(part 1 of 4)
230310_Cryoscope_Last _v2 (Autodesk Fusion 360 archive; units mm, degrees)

design "230310_Cryoscope_Last" references "P300_M-Step", "001_LED_Input", "001_CM_Imaging", "001_CM_Excitation", "DIN912 M4 x 18", "VAP4_M-Step", "Arduino Triggerbox main", "MB3045_M-Step", "Zeiss_CMS_mount", "Zeiss_dovetail", "LED_combiner_mount", "001_CM_Objective", "DIN912 M4 x 48", "Optical Table Assembly", "Linkam stage approximate", "M4 Hex nut"
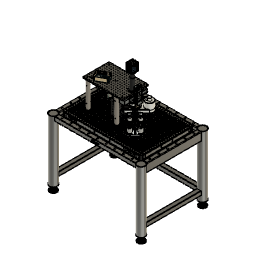
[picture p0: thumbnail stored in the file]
component_insert "Component Insert2"
sketch "Sketch1" plane through (0, 0, -72.86) normal (0, 0, 1) x axis (-1, 0, 0)
  line L1 (-212.7048, -83.1723) -> (-237.1448, -83.1723)
  line L2 (-212.7048, -59.1973) -> (-212.7048, -83.1723)
  line L3 (-177.1448, -52.8473) -> (-206.3548, -52.8473)
  line L4 (-177.1448, 7.1527) -> (-177.1448, -52.8473)
  line L5 (-206.3548, 7.1527) -> (-177.1448, 7.1527)
  line L6 (-212.7048, 37.4777) -> (-212.7048, 13.5027)
  line L7 (-237.1448, 37.4777) -> (-212.7048, 37.4777)
  line L8 (-237.1448, -83.1723) -> (-237.1448, 37.4777)
  arc A1 centre (-206.3548, -59.1973) radius 6.35 clockwise from (-212.7048, -59.1973) to (-206.3548, -52.8473)
  arc A2 centre (-206.3548, 13.5027) radius 6.35 clockwise from (-206.3548, 7.1527) to (-212.7048, 13.5027)
  circle C1 centre (-197.3988, -22.8473) radius 19.05
  circle C2 centre (-227.1372, -72.8472) radius 4
  circle C3 centre (-227.1372, 27.1526) radius 4
component_insert "Component Insert10"
component_insert "Component Insert11"
base_feature "Base Feature"
component_insert "Component Insert13"
component_insert "Component Insert14"
component_insert "Component Insert15"
component_insert "Component Insert18"
component_insert "Component Insert19"
position "Position3"
sketch "Sketch2" plane through (0, 0, -72.86) normal (0, 0, 1) x axis (-1, 0, 0)
  line L1 (-212.7048, -83.1723) -> (-237.1448, -83.1723)
  line L2 (-212.7048, -59.1973) -> (-212.7048, -83.1723)
  line L3 (-177.1448, -52.8473) -> (-206.3548, -52.8473)
  line L4 (-177.1448, 7.1527) -> (-177.1448, -52.8473)
  line L5 (-206.3548, 7.1527) -> (-177.1448, 7.1527)
  line L6 (-212.7048, 37.4777) -> (-212.7048, 13.5027)
  line L7 (-237.1448, 37.4777) -> (-212.7048, 37.4777)
  line L8 (-237.1448, -83.1723) -> (-237.1448, 37.4777)
  arc A1 centre (-206.3548, -59.1973) radius 6.35 clockwise from (-212.7048, -59.1973) to (-206.3548, -52.8473)
  arc A2 centre (-206.3548, 13.5027) radius 6.35 clockwise from (-206.3548, 7.1527) to (-212.7048, 13.5027)
  circle C1 centre (-197.3988, -22.8473) radius 19.05
  circle C2 centre (-227.1372, -72.8472) radius 4
  circle C3 centre (-227.1372, 27.1526) radius 4
position "Position4"
position "Position5"
sketch "Sketch3" plane through (0, 0, -57.0351) normal (0, 0, 1) x axis (-1, 0, 0)
  line L1 (217.4329, 123.3513) -> (217.4329, -170.6487)
  line L2 (-229.2671, 126.0513) -> (214.7329, 126.0513)
  line L3 (-231.9671, -170.6487) -> (-231.9671, 123.3513)
  line L4 (214.7329, -173.3487) -> (-229.2671, -173.3487)
  line L5 (-197.2572, -57.4246) -> (-191.069, -57.3992)
  line L6 (-192.2572, -57.4245) -> (-192.2573, -57.4041)
  line L7 (-192.2686, -57.4246) -> (-192.2572, -57.4245)
  line L8 (-197.5509, 11.7299) -> (-191.9849, 11.7277)
  line L9 (-192.1795, -4.5263) -> (-192.3988, -22.8473)
  line L10 (-247.6902, -49.1676) -> (-137.1074, -49.1676)
  line L11 (-247.6902, 3.473) -> (-247.6902, -49.1676)
  line L12 (-137.1074, 3.473) -> (-247.6902, 3.473)
  line L13 (-137.1074, -49.1676) -> (-137.1074, 3.473)
  line L14 (-247.6902, 3.473) -> (-137.1074, -49.1676)
  line L15 (-137.1074, 3.473) -> (-247.6902, -49.1676)
  circle C1 centre (-197.3988, -22.8473) radius 19.05
  arc A1 centre (214.7329, -170.6487) radius 2.7 clockwise from (217.4329, -170.6487) to (214.7329, -173.3487)
  arc A2 centre (214.7329, 123.3513) radius 2.7 clockwise from (214.7329, 126.0513) to (217.4329, 123.3513)
  arc A3 centre (-229.2671, 123.3513) radius 2.7 clockwise from (-231.9671, 123.3513) to (-229.2671, 126.0513)
  arc A4 centre (-229.2671, -170.6487) radius 2.7 clockwise from (-229.2671, -173.3487) to (-231.9671, -170.6487)
  circle C2 centre (205.2329, 113.8513) radius 3.5
  circle C3 centre (205.2329, 88.8513) radius 3.5
  circle C4 centre (205.2329, 63.8513) radius 3.5
  circle C5 centre (205.2329, 38.8513) radius 3.5
  circle C6 centre (205.2329, 13.8513) radius 3.5
  circle C7 centre (205.2329, -11.1487) radius 3.5
  circle C8 centre (205.2329, -36.1487) radius 3.5
  circle C9 centre (205.2329, -61.1487) radius 3.5
  circle C10 centre (205.2329, -86.1487) radius 3.5
  circle C11 centre (205.2329, -111.1487) radius 3.5
  circle C12 centre (205.2329, -136.1487) radius 3.5
  circle C13 centre (205.2329, -161.1487) radius 3.5
  circle C14 centre (180.2329, 113.8513) radius 3.5
  circle C15 centre (180.2329, 88.8513) radius 3.5
  circle C16 centre (180.2329, 63.8513) radius 3.5
  circle C17 centre (180.2329, 38.8513) radius 3.5
  circle C18 centre (180.2329, 13.8513) radius 3.5
  circle C19 centre (180.2329, -11.1487) radius 3.5
  circle C20 centre (180.2329, -36.1487) radius 3.5
  circle C21 centre (180.2329, -61.1487) radius 3.5
  circle C22 centre (180.2329, -86.1487) radius 3.5
  circle C23 centre (180.2329, -111.1487) radius 3.5
  circle C24 centre (180.2329, -136.1487) radius 3.5
  circle C25 centre (180.2329, -161.1487) radius 3.5
  circle C26 centre (155.2329, 113.8513) radius 3.5
  circle C27 centre (155.2329, 88.8513) radius 3.5
  circle C28 centre (155.2329, 63.8513) radius 3.5
  circle C29 centre (155.2329, 38.8513) radius 3.5
  circle C30 centre (155.2329, 13.8513) radius 3.5
  circle C31 centre (155.2329, -11.1487) radius 3.5
  circle C32 centre (155.2329, -36.1487) radius 3.5
  circle C33 centre (155.2329, -61.1487) radius 3.5
  circle C34 centre (155.2329, -86.1487) radius 3.5
  circle C35 centre (155.2329, -111.1487) radius 3.5
  circle C36 centre (155.2329, -136.1487) radius 3.5
  circle C37 centre (155.2329, -161.1487) radius 3.5
  circle C38 centre (130.2329, 113.8513) radius 3.5
  circle C39 centre (130.2329, 88.8513) radius 3.5
  circle C40 centre (130.2329, 63.8513) radius 3.5
  circle C41 centre (130.2329, 38.8513) radius 3.5
  circle C42 centre (130.2329, 13.8513) radius 3.5
  circle C43 centre (130.2329, -11.1487) radius 3.5
  circle C44 centre (130.2329, -36.1487) radius 3.5
  circle C45 centre (130.2329, -61.1487) radius 3.5
  circle C46 centre (130.2329, -86.1487) radius 3.5
  circle C47 centre (130.2329, -111.1487) radius 3.5
  circle C48 centre (130.2329, -136.1487) radius 3.5
  circle C49 centre (130.2329, -161.1487) radius 3.5
  circle C50 centre (105.2329, 113.8513) radius 3.5
  circle C51 centre (105.2329, 88.8513) radius 3.5
  circle C52 centre (105.2329, 63.8513) radius 3.5
  circle C53 centre (105.2329, 38.8513) radius 3.5
  circle C54 centre (105.2329, 13.8513) radius 3.5
  circle C55 centre (105.2329, -11.1487) radius 3.5
  circle C56 centre (105.2329, -36.1487) radius 3.5
  circle C57 centre (105.2329, -61.1487) radius 3.5
  circle C58 centre (105.2329, -86.1487) radius 3.5
  circle C59 centre (105.2329, -111.1487) radius 3.5
  circle C60 centre (105.2329, -136.1487) radius 3.5
  circle C61 centre (105.2329, -161.1487) radius 3.5
  circle C62 centre (80.2329, 113.8513) radius 3.5
  circle C63 centre (80.2329, 88.8513) radius 3.5
  circle C64 centre (80.2329, 63.8513) radius 3.5
  circle C65 centre (80.2329, 38.8513) radius 3.5
  circle C66 centre (80.2329, 13.8513) radius 3.5
  circle C67 centre (80.2329, -11.1487) radius 3.5
  circle C68 centre (80.2329, -36.1487) radius 3.5
  circle C69 centre (80.2329, -61.1487) radius 3.5
  circle C70 centre (80.2329, -86.1487) radius 3.5
  circle C71 centre (80.2329, -111.1487) radius 3.5
  circle C72 centre (80.2329, -136.1487) radius 3.5
  circle C73 centre (80.2329, -161.1487) radius 3.5
  circle C74 centre (55.2329, 113.8513) radius 3.5
  circle C75 centre (55.2329, 88.8513) radius 3.5
  circle C76 centre (55.2329, 63.8513) radius 3.5
  circle C77 centre (55.2329, 38.8513) radius 3.5
  circle C78 centre (55.2329, 13.8513) radius 3.5
  circle C79 centre (55.2329, -11.1487) radius 3.5
  circle C80 centre (55.2329, -36.1487) radius 3.5
  circle C81 centre (55.2329, -61.1487) radius 3.5
  circle C82 centre (55.2329, -86.1487) radius 3.5
  circle C83 centre (55.2329, -111.1487) radius 3.5
  circle C84 centre (55.2329, -136.1487) radius 3.5
  circle C85 centre (55.2329, -161.1487) radius 3.5
  circle C86 centre (30.2329, 113.8513) radius 3.5
  circle C87 centre (30.2329, 88.8513) radius 3.5
  circle C88 centre (30.2329, 63.8513) radius 3.5
  circle C89 centre (30.2329, 38.8513) radius 3.5
  circle C90 centre (30.2329, 13.8513) radius 3.5
  circle C91 centre (30.2329, -11.1487) radius 3.5
  circle C92 centre (30.2329, -36.1487) radius 3.5
  circle C93 centre (30.2329, -61.1487) radius 3.5
  circle C94 centre (30.2329, -86.1487) radius 3.5
  circle C95 centre (30.2329, -111.1487) radius 3.5
  circle C96 centre (30.2329, -136.1487) radius 3.5
  circle C97 centre (30.2329, -161.1487) radius 3.5
  circle C98 centre (5.2329, 113.8513) radius 3.5
  circle C99 centre (5.2329, 88.8513) radius 3.5
  circle C100 centre (5.2329, 63.8513) radius 3.5
  circle C101 centre (5.2329, 38.8513) radius 3.5
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  point P235 (-192.3988, -22.8473)
  point P236 (-192.3988, -22.8473)
  point P243 (-192.7855, 11.728)
  point P244 (-197.2195, 11.7298)
  point P245 (-192.1795, -4.5263)
  point P246 (-193.4456, -57.409)
  point P247 (-192.2573, -57.4041)
  point P252 (-192.3988, -22.8473)
  point P2 (-197.3988, -22.8473)
  coincident P235 P236
  perpendicular L5 L6
  coincident L8 P243
  coincident L8 P244
  coincident C1 P245
  coincident L5 P246
  coincident L5 P247
  horizontal L10
  perpendicular L10 L11
  parallel L10 L12
  parallel L11 L13
  coincident L14 P252
  coincident L15 P252
  coincident P235 P252
  dimension "d3" distance P2 P235 = 5
  dimension "d4" diameter = 69.155
position "Position6"
component_insert "Component Insert21"
position "Position7"
component_insert "Component Insert22"
component_insert "Component Insert23"
position "Position8"
component_insert "Component Insert25"
component_insert "Component Insert28"
component_insert "Component Insert29"
component_insert "Component Insert30"
component_insert "Component Insert31"
component_insert "Component Insert32"
component_insert "Component Insert33"
component_insert "Component Insert34"
component_insert "Component Insert35"
position "Position9"
component_insert "Component Insert38"
component_insert "Component Insert39"
position "Position10"
sketch "Sketch5" plane through (4.0554, 0, -4.0554) normal (-0.7071, 0, 0.7071) x axis (0, -1, 0)
  line L1 (-39.0974, -127.7737) -> (-39.0974, -152.2737)
  line L2 (-6.5974, -127.7737) -> (-39.0974, -127.7737)
  line L3 (-6.5974, -152.2737) -> (-6.5974, -127.7737)
  line L4 (-39.0974, -152.2737) -> (-6.5974, -152.2737)
  line L5 (-70.3474, -125.4379) -> (24.6526, -125.4379)
  line L6 (-70.3474, -154.0237) -> (-70.3474, -125.4379)
  line L7 (24.6526, -154.0237) -> (-70.3474, -154.0237)
  line L8 (24.6526, -125.4379) -> (24.6526, -154.0237)
  line L9 (-7.0974, -127.7737) -> (-39.0974, -127.7737)
  line L10 (-7.0974, -151.7737) -> (-7.0974, -127.7737)
  line L11 (-39.0974, -151.7737) -> (-7.0974, -151.7737)
  line L12 (-39.0974, -127.7737) -> (-39.0974, -151.7737)
  point P3 (-39.0974, -127.7737)
  point P10 (-39.0974, -127.7737)
  point P11 (-7.0974, -127.7737)
  point P13 (-39.0974, -151.7737)
  horizontal L9
  vertical L10
  horizontal L11
  vertical L12
  coincident P3 P10
  dimension "d7" distance P10 P11 = 32
  dimension "d8" distance P10 P13 = 24
extrude "Extrude2" new body sketch "Sketch5" profile of L1 L2 L9 L10 L11 L12 along normal blind 0.1
move "Move1"
move "Move2"
move "Move3" TranslateX 0 TranslateY 0.25 TranslateZ 0
component_insert "Component Insert40"
component_insert "Component Insert41"
position "Position11"
position "Position12"
move "Move4"
move "Move5"
move "Move6"
position "Position13"
move "Move7"
move "Move8"
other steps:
create_component "CreateComponent2"

design "MIM4-OSxxx (CATALOG MODEL)"
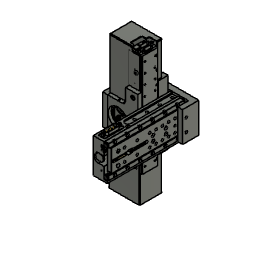
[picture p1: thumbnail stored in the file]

design "LBF254-075-Step"
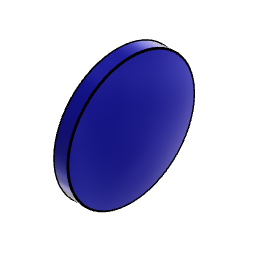
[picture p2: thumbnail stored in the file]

design "DIN912 M4 x 18"
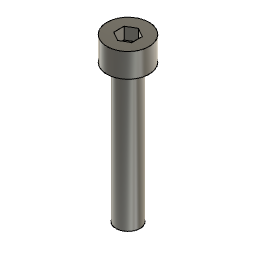
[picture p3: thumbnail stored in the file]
base_feature "Base Feature"
extrude "Extrude1" add of existing geometry blind 5

design "Grounding strip"
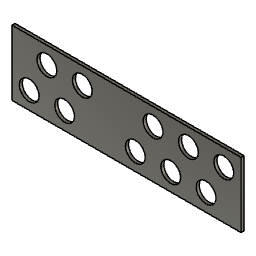
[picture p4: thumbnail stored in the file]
base_feature "Base Feature"

design "SM1FCA-Step"
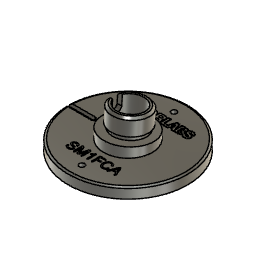
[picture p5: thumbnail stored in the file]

design "C60-3060-C-MOUNT (CATALOG MODEL)"
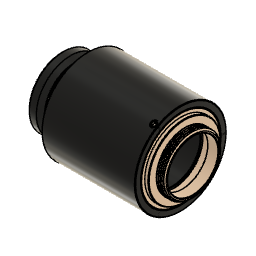
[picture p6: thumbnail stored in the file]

design "Arduino Leonardo"
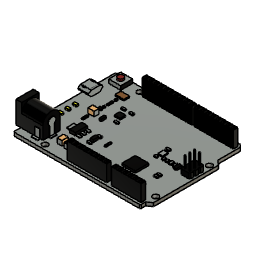
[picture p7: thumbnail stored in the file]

design "TR50_M-Step"
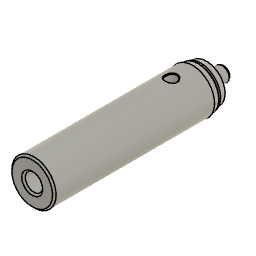
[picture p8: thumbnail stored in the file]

design "Optical Table Assembly" references "SDP6090-Step", "B6090L-Step (1)"
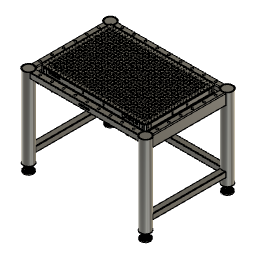
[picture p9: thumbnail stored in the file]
parameter "d4_1" = -3
parameter "d2_2" = 5
parameter "d3_3" = 0
parameter "d5_2" = 53
parameter "d8_1" = 5
parameter "d9_1" = 0
parameter "d10_1" = 8
parameter "d11_1" = 5
parameter "d12_1" = -3
parameter "d13_1" = 0
parameter "d15_1" = 6.25
parameter "d17_1" = -2
parameter "d18_1" = 0
parameter "d20_1" = -2
parameter "d21_1" = 0
parameter "d22_1" = 0.5
parameter "d23_1" = 0.2
parameter "d24_1" = -0.1
parameter "d26_1" = 2
parameter "d27_1" = 0
parameter "d29_1" = 1
parameter "d31_1" = 4
parameter "d32_1" = 2.5
parameter "d33_1" = 2.5
parameter "d34_1" = 0
parameter "d35_1" = 0
parameter "d1" = 70
parameter "d2" = 0
parameter "d3_1" = 17.3
parameter "d5" = 0
parameter "d1_1" = 95
parameter "d2_1" = 153
parameter "d3_2" = 15
parameter "d5_1" = 7.7
parameter "d7" = 3
parameter "d8" = 36.5
parameter "d9" = 0
parameter "d10" = 60
parameter "d11" = 0
parameter "d12" = 42
parameter "d13" = 47
parameter "d14" = 17
parameter "d15" = 28
parameter "d16" = 0
parameter "d18" = 20
parameter "d19" = 4
parameter "d20" = -5
parameter "d21" = 0
parameter "d22" = 2
parameter "d23" = 4.5
parameter "d24" = 0
parameter "d25" = 5
parameter "d26" = 0
parameter "d27" = 14
parameter "d28" = -70
parameter "d29" = 0
parameter "d30" = 12
parameter "d31" = 21
parameter "d33" = 1
parameter "d35" = 2
parameter "d37" = 4
parameter "d38" = 59 (= "61 mm - 2 mm")
parameter "d39" = 81
parameter "d40" = -3.28
parameter "d41" = 0
parameter "d42" = 58.28
parameter "d43" = -22.2
parameter "d44" = 0
parameter "d45" = 60.48 (= "58.280 mm + 2.2 mm")
parameter "d46" = 100
parameter "d49" = 56
parameter "d52" = -10
parameter "d53" = 0
parameter "d54" = -11.02
parameter "d55" = 0
parameter "d58" = -0.5
parameter "d59" = 0
parameter "d60" = 21.6
parameter "d61" = 10.8 (= "( 21.6 / 2 ) * 1 mm")
parameter "d62" = 10.8 (= "( 21.6 / 2 ) * 1 mm")
parameter "d63" = 2
parameter "d64" = 0.5
parameter "d65" = 0
parameter "d66" = -1
parameter "d67" = 9.5
parameter "d68" = 0
parameter "d69" = 6
parameter "d70" = 7
parameter "d71" = 0
parameter "d72" = 0.5
parameter "d73" = 1
parameter "d74" = 4
parameter "d75" = -1
parameter "d76" = 0
parameter "d1_2" = 25
parameter "d4_2" = 30
parameter "d6" = 0
parameter "d7_1" = 13
parameter "d16_1" = 13
parameter "d19_1" = 3
parameter "d25_1" = 3
parameter "d47" = 100
parameter "d48" = 0
parameter "d50" = 100
parameter "d51" = 0
parameter "d56" = 100
parameter "d57" = 0
parameter "d77" = 100
parameter "d78" = 0
component_insert "Component Insert1" AlongDistance 15 TaperAngle 0
component_insert "Component Insert2"
position "Position1"
position "Position2"
sketch "Sketch1" plane through (0, 0, 1006.549) normal (0, 0, 1) x axis (-1, 0, 0)
  line L1 (395.1988, 26.6561) -> (395.1988, 470.6561)
  line L2 (541.8988, 23.9561) -> (397.8988, 23.9561)
  line L3 (544.5988, 470.6561) -> (544.5988, 26.6561)
  line L4 (397.8988, 473.3561) -> (541.8988, 473.3561)
  arc A1 centre (397.8988, 470.6561) radius 2.7 clockwise from (395.1988, 470.6561) to (397.8988, 473.3561)
  arc A2 centre (397.8988, 26.6561) radius 2.7 clockwise from (397.8988, 23.9561) to (395.1988, 26.6561)
  arc A3 centre (541.8988, 26.6561) radius 2.7 clockwise from (544.5988, 26.6561) to (541.8988, 23.9561)
  arc A4 centre (541.8988, 470.6561) radius 2.7 clockwise from (541.8988, 473.3561) to (544.5988, 470.6561)
  circle C1 centre (532.3988, 461.1561) radius 3.5
  circle C2 centre (507.3988, 461.1561) radius 3.5
  circle C3 centre (482.3988, 461.1561) radius 3.5
  circle C4 centre (457.3988, 461.1561) radius 3.5
  circle C5 centre (432.3988, 461.1561) radius 3.5
  circle C6 centre (407.3988, 461.1561) radius 3.5
  circle C7 centre (532.3988, 436.1561) radius 3.5
  circle C8 centre (507.3988, 436.1561) radius 3.5
  circle C9 centre (482.3988, 436.1561) radius 3.5
  circle C10 centre (457.3988, 436.1561) radius 3.5
  circle C11 centre (432.3988, 436.1561) radius 3.5
  circle C12 centre (407.3988, 436.1561) radius 3.5
  circle C13 centre (532.3988, 411.1561) radius 3.5
  circle C14 centre (507.3988, 411.1561) radius 3.5
  circle C15 centre (482.3988, 411.1561) radius 3.5
  circle C16 centre (457.3988, 411.1561) radius 3.5
  circle C17 centre (432.3988, 411.1561) radius 3.5
  circle C18 centre (407.3988, 411.1561) radius 3.5
  circle C19 centre (532.3988, 386.1561) radius 3.5
  circle C20 centre (507.3988, 386.1561) radius 3.5
  circle C21 centre (482.3988, 386.1561) radius 3.5
  circle C22 centre (457.3988, 386.1561) radius 3.5
  circle C23 centre (432.3988, 386.1561) radius 3.5
  circle C24 centre (407.3988, 386.1561) radius 3.5
  circle C25 centre (532.3988, 361.1561) radius 3.5
  circle C26 centre (507.3988, 361.1561) radius 3.5
  circle C27 centre (482.3988, 361.1561) radius 3.5
  circle C28 centre (457.3988, 361.1561) radius 3.5
  circle C29 centre (432.3988, 361.1561) radius 3.5
  circle C30 centre (407.3988, 361.1561) radius 3.5
  circle C31 centre (532.3988, 336.1561) radius 3.5
  circle C32 centre (507.3988, 336.1561) radius 3.5
  circle C33 centre (482.3988, 336.1561) radius 3.5
  circle C34 centre (457.3988, 336.1561) radius 3.5
  circle C35 centre (432.3988, 336.1561) radius 3.5
  circle C36 centre (407.3988, 336.1561) radius 3.5
  circle C37 centre (532.3988, 311.1561) radius 3.5
  circle C38 centre (507.3988, 311.1561) radius 3.5
  circle C39 centre (482.3988, 311.1561) radius 3.5
  circle C40 centre (457.3988, 311.1561) radius 3.5
  circle C41 centre (432.3988, 311.1561) radius 3.5
  circle C42 centre (407.3988, 311.1561) radius 3.5
  circle C43 centre (532.3988, 286.1561) radius 3.5
  circle C44 centre (507.3988, 286.1561) radius 3.5
  circle C45 centre (482.3988, 286.1561) radius 3.5
  circle C46 centre (457.3988, 286.1561) radius 3.5
  circle C47 centre (432.3988, 286.1561) radius 3.5
  circle C48 centre (407.3988, 286.1561) radius 3.5
  circle C49 centre (532.3988, 261.1561) radius 3.5
  circle C50 centre (507.3988, 261.1561) radius 3.5
  circle C51 centre (482.3988, 261.1561) radius 3.5
  circle C52 centre (457.3988, 261.1561) radius 3.5
  circle C53 centre (432.3988, 261.1561) radius 3.5
  circle C54 centre (407.3988, 261.1561) radius 3.5
  circle C55 centre (532.3988, 236.1561) radius 3.5
  circle C56 centre (507.3988, 236.1561) radius 3.5
  circle C57 centre (482.3988, 236.1561) radius 3.5
  circle C58 centre (457.3988, 236.1561) radius 3.5
  circle C59 centre (432.3988, 236.1561) radius 3.5
  circle C60 centre (407.3988, 236.1561) radius 3.5
  circle C61 centre (532.3988, 211.1561) radius 3.5
  circle C62 centre (507.3988, 211.1561) radius 3.5
  circle C63 centre (482.3988, 211.1561) radius 3.5
  circle C64 centre (457.3988, 211.1561) radius 3.5
  circle C65 centre (432.3988, 211.1561) radius 3.5
  circle C66 centre (407.3988, 211.1561) radius 3.5
  circle C67 centre (532.3988, 186.1561) radius 3.5
  circle C68 centre (507.3988, 186.1561) radius 3.5
  circle C69 centre (482.3988, 186.1561) radius 3.5
  circle C70 centre (457.3988, 186.1561) radius 3.5
  circle C71 centre (432.3988, 186.1561) radius 3.5
  circle C72 centre (407.3988, 186.1561) radius 3.5
  circle C73 centre (532.3988, 161.1561) radius 3.5
  circle C74 centre (507.3988, 161.1561) radius 3.5
  circle C75 centre (482.3988, 161.1561) radius 3.5
  circle C76 centre (457.3988, 161.1561) radius 3.5
  circle C77 centre (432.3988, 161.1561) radius 3.5
  circle C78 centre (407.3988, 161.1561) radius 3.5
  circle C79 centre (532.3988, 136.1561) radius 3.5
  circle C80 centre (507.3988, 136.1561) radius 3.5
  circle C81 centre (482.3988, 136.1561) radius 3.5
  circle C82 centre (457.3988, 136.1561) radius 3.5
  circle C83 centre (432.3988, 136.1561) radius 3.5
  circle C84 centre (407.3988, 136.1561) radius 3.5
  circle C85 centre (532.3988, 111.1561) radius 3.5
  circle C86 centre (507.3988, 111.1561) radius 3.5
  circle C87 centre (482.3988, 111.1561) radius 3.5
  circle C88 centre (457.3988, 111.1561) radius 3.5
  circle C89 centre (432.3988, 111.1561) radius 3.5
  circle C90 centre (407.3988, 111.1561) radius 3.5
  circle C91 centre (532.3988, 86.1561) radius 3.5
  circle C92 centre (507.3988, 86.1561) radius 3.5
  circle C93 centre (482.3988, 86.1561) radius 3.5
  circle C94 centre (457.3988, 86.1561) radius 3.5
  circle C95 centre (432.3988, 86.1561) radius 3.5
  circle C96 centre (407.3988, 86.1561) radius 3.5
  circle C97 centre (532.3988, 61.1561) radius 3.5
  circle C98 centre (507.3988, 61.1561) radius 3.5
  circle C99 centre (482.3988, 61.1561) radius 3.5
  circle C100 centre (457.3988, 61.1561) radius 3.5
  circle C101 centre (432.3988, 61.1561) radius 3.5
  circle C102 centre (407.3988, 61.1561) radius 3.5
  circle C103 centre (532.3988, 36.1561) radius 3.5
  circle C104 centre (507.3988, 36.1561) radius 3.5
  circle C105 centre (482.3988, 36.1561) radius 3.5
  circle C106 centre (457.3988, 36.1561) radius 3.5
  circle C107 centre (432.3988, 36.1561) radius 3.5
  circle C108 centre (407.3988, 36.1561) radius 3.5
  circle C109 centre (419.8988, 48.6561) radius 3.3
  circle C110 centre (519.8988, 48.6561) radius 3.3
  circle C111 centre (469.8988, 248.6561) radius 3.3
  circle C112 centre (519.8988, 448.6561) radius 3.3
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position "Position2"
sketch "Sketch2" plane through (0, 0, 0) normal (0, 0, 1) x axis (1, 0, 0)
  line L1 (-137.3539, -400) -> (-375, -400)
  line L2 (-137.3539, -541.0776) -> (-137.3539, -400)
  line L3 (-375, -541.0776) -> (-137.3539, -541.0776)
  line L4 (-375, -400) -> (-375, -541.0776)
  horizontal L1
  vertical L2
  horizontal L3
  vertical L4

design "Arduino Triggerbox main" references "Grounding strip", "LED_R", "Arduino Leonardo", "LED_G", "Connector_Ass_Step", "USB_A_FEM"
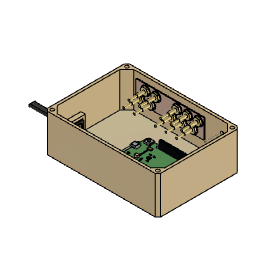
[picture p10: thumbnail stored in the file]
component_insert "Component Insert1"
sketch "Sketch1" plane through (0, 0, 0) normal (0, 0, 1) x axis (1, 0, 0)
  line L1 (68.627, 0) -> (0, 0)
  line L2 (68.627, -53.52) -> (68.627, 0)
  line L3 (0, -53.52) -> (68.627, -53.52)
  line L4 (0, 0) -> (0, -53.52)
  line L5 (-30, 0) -> (0, 0)
  line L6 (-30, 30) -> (-30, 0)
  line L7 (0, 30) -> (-30, 30)
  line L8 (0, 0) -> (0, 30)
  line L9 (98.627, -53.52) -> (68.627, -53.52)
  line L10 (98.627, -83.52) -> (98.627, -53.52)
  line L11 (68.627, -83.52) -> (98.627, -83.52)
  line L12 (68.627, -53.52) -> (68.627, -83.52)
  line L13 (98.627, 30) -> (-30, 30)
  line L14 (98.627, -83.52) -> (98.627, 30)
  line L15 (-30, -83.52) -> (98.627, -83.52)
  line L16 (-30, 30) -> (-30, -83.52)
  point P1 (0, 0)
  point P2 (0, 0)
  point P6 (0, 0)
  point P7 (-30, 0)
  point P9 (0, 30)
  point P4 (68.627, -53.52)
  point P10 (98.627, -53.52)
  point P12 (68.627, -83.52)
  horizontal L1
  vertical L2
  horizontal L3
  vertical L4
  coincident P1 P2
  horizontal L5
  vertical L6
  horizontal L7
  vertical L8
  coincident P1 P6
  horizontal L9
  vertical L10
  horizontal L11
  vertical L12
  horizontal L13
  vertical L14
  horizontal L15
  vertical L16
  dimension "d1" distance P6 P7 = 30
  dimension "d2" distance P6 P9 = 30
  dimension "d3" distance P4 P10 = 30
  dimension "d4" distance P4 P12 = 30
  dimension "d59" = 6
extrude "Extrude1" new body sketch "Sketch1" against normal blind 2
sketch "Sketch2" plane through (0, 0, 1.8) normal (0, 0, 1) x axis (-1, 0, 0)
  line L1 (-11.5, 43.4) -> (-11.5, 40.5)
  line L2 (-12.8, 43.4) -> (-11.5, 43.4)
  line L3 (-12.8, 46.7) -> (-12.8, 43.4)
  line L4 (-11.5, 46.7) -> (-12.8, 46.7)
  line L5 (-11.5, 49.5) -> (-11.5, 46.7)
  line L6 (-10.3, 49.5) -> (-11.5, 49.5)
  line L7 (-10.3, 51) -> (-10.3, 49.5)
  line L8 (-6.8, 51) -> (-10.3, 51)
  line L9 (-6.8, 49.5) -> (-6.8, 51)
  line L10 (0, 49.5) -> (-6.8, 49.5)
  line L11 (0, 52.8) -> (0, 49.5)
  line L12 (-65.5, 53.3) -> (-0.5, 53.3)
  line L13 (-66, 50.5) -> (-66, 52.8)
  line L14 (-68.4, 48.8) -> (-66, 50.5)
  line L15 (-68.4, 15) -> (-68.4, 48.8)
  line L16 (-66, 13) -> (-68.4, 15)
  line L17 (-66, 1.2) -> (-66, 13)
  line L18 (-64.8, 0) -> (-66, 1.2)
  line L19 (-0.5, 0) -> (-64.8, 0)
  line L20 (0, 12.7) -> (0, 0.5)
  line L21 (-4.5, 12.7) -> (0, 12.7)
  line L22 (-4.5, 17.3) -> (-4.5, 12.7)
  line L23 (0, 17.3) -> (-4.5, 17.3)
  line L24 (0, 40.5) -> (0, 17.3)
  line L25 (-11.5, 40.5) -> (0, 40.5)
  line L26 (-15, 37.943) -> (-15, 39.1)
  line L27 (-12.3201, 37.943) -> (-15, 37.943)
  line L28 (-12.3201, 34.1028) -> (-12.3201, 37.943)
  line L29 (-15, 34.1028) -> (-12.3201, 34.1028)
  line L30 (-15, 32.8) -> (-15, 34.1028)
  line L31 (-18, 32.8) -> (-15, 32.8)
  line L32 (-18, 32.9969) -> (-18, 32.8)
  line L33 (-20.2563, 32.9969) -> (-18, 32.9969)
  line L34 (-20.2563, 34.1969) -> (-20.2563, 32.9969)
  line L35 (-18, 34.1969) -> (-20.2563, 34.1969)
  line L36 (-18, 35.4062) -> (-18, 34.1969)
  line L37 (-20.2563, 35.4062) -> (-18, 35.4062)
  line L38 (-20.2563, 36.6062) -> (-20.2563, 35.4062)
  line L39 (-18, 36.6062) -> (-20.2563, 36.6062)
  line L40 (-18, 37.7253) -> (-18, 36.6062)
  line L41 (-20.2563, 37.7253) -> (-18, 37.7253)
  line L42 (-20.2563, 38.9253) -> (-20.2563, 37.7253)
  line L43 (-18, 38.9253) -> (-20.2563, 38.9253)
  line L44 (-18, 39.1) -> (-18, 38.9253)
  line L45 (-15, 39.1) -> (-18, 39.1)
  line L46 (-3.2, 33.5) -> (-5.2, 33.5)
  line L47 (-3.2, 32.3) -> (-3.2, 33.5)
  line L48 (-5.2, 32.3) -> (-3.2, 32.3)
  line L49 (-5.2, 33.5) -> (-5.2, 32.3)
  line L50 (-3.2, 25.8) -> (-5.2, 25.8)
  line L51 (-3.2, 24.6) -> (-3.2, 25.8)
  line L52 (-5.2, 24.6) -> (-3.2, 24.6)
  line L53 (-5.2, 25.8) -> (-5.2, 24.6)
  line L54 (-17.15, 25.9) -> (-18.25, 25.9)
  line L55 (-17.15, 23.2) -> (-17.15, 25.9)
  line L56 (-18.25, 23.2) -> (-17.15, 23.2)
  line L57 (-18.25, 25.9) -> (-18.25, 23.2)
  line L58 (-11.05, 25.6036) -> (-14.25, 25.6036)
  line L59 (-11.05, 23.1036) -> (-11.05, 25.6036)
  line L60 (-14.25, 23.1036) -> (-11.05, 23.1036)
  line L61 (-14.25, 25.6036) -> (-14.25, 23.1036)
  line L62 (-11.9692, 29.9799) -> (-12.8299, 29.9799)
  line L63 (-11.9692, 26.7892) -> (-11.9692, 29.9799)
  line L64 (-12.8299, 26.7892) -> (-11.9692, 26.7892)
  line L65 (-12.8299, 29.9799) -> (-12.8299, 26.7892)
  line L66 (-12.2, 17.2036) -> (-13, 17.2036)
  line L67 (-12.2, 14.0036) -> (-12.2, 17.2036)
  line L68 (-13, 14.0036) -> (-12.2, 14.0036)
  line L69 (-13, 17.2036) -> (-13, 14.0036)
  line L70 (-10.3, 10.7) -> (-14.8, 10.7)
  line L71 (-10.3, 7.7) -> (-10.3, 10.7)
  line L72 (-14.8, 7.7) -> (-10.3, 7.7)
  line L73 (-14.8, 10.7) -> (-14.8, 7.7)
  line L74 (-24, 37.35) -> (-25.6, 37.35)
  line L75 (-24, 34.4854) -> (-24, 37.35)
  line L76 (-25.6, 34.4854) -> (-24, 34.4854)
  line L77 (-25.6, 37.35) -> (-25.6, 34.4854)
  line L78 (-21.9, 15.2) -> (-23.9, 15.2)
  line L79 (-21.9, 14.2) -> (-21.9, 15.2)
  line L80 (-23.9, 14.2) -> (-21.9, 14.2)
  line L81 (-23.9, 15.2) -> (-23.9, 14.2)
  line L82 (-23.9, 39.1) -> (-25.9, 39.1)
  line L83 (-23.9, 38.1) -> (-23.9, 39.1)
  line L84 (-25.9, 38.1) -> (-23.9, 38.1)
  line L85 (-25.9, 39.1) -> (-25.9, 38.1)
  line L86 (-21.9, 23) -> (-23.9, 23)
  line L87 (-21.9, 22) -> (-21.9, 23)
  line L88 (-23.9, 22) -> (-21.9, 22)
  line L89 (-23.9, 23) -> (-23.9, 22)
  line L90 (-57.0515, 44.5) -> (-58.0515, 44.5)
  line L91 (-57.0515, 42.5) -> (-57.0515, 44.5)
  line L92 (-58.0515, 42.5) -> (-57.0515, 42.5)
  line L93 (-58.0515, 44.5) -> (-58.0515, 42.5)
  line L94 (-56.6, 35.5) -> (-58.6, 35.5)
  line L95 (-56.6, 34.5) -> (-56.6, 35.5)
  line L96 (-58.6, 34.5) -> (-56.6, 34.5)
  line L97 (-58.6, 35.5) -> (-58.6, 34.5)
  line L98 (-47.5517, 21.7683) -> (-49.5517, 21.7683)
  line L99 (-47.5517, 20.7683) -> (-47.5517, 21.7683)
  line L100 (-49.5517, 20.7683) -> (-47.5517, 20.7683)
  line L101 (-49.5517, 21.7683) -> (-49.5517, 20.7683)
  line L102 (-51.2, 27.4683) -> (-52.2, 27.4683)
  line L103 (-51.2, 25.8683) -> (-51.2, 27.4683)
  line L104 (-52.2, 25.8683) -> (-51.2, 25.8683)
  line L105 (-52.2, 27.4683) -> (-52.2, 25.8683)
  line L106 (-54.8, 27.5683) -> (-56.1, 27.5683)
  line L107 (-54.8, 25.5683) -> (-54.8, 27.5683)
  line L108 (-56.1, 25.5683) -> (-54.8, 25.5683)
  line L109 (-56.1, 27.5683) -> (-56.1, 25.5683)
  line L110 (-58.2, 28.3683) -> (-59.9, 28.3683)
  line L111 (-58.2, 25.3683) -> (-58.2, 28.3683)
  line L112 (-59.9, 25.3683) -> (-58.2, 25.3683)
  line L113 (-59.9, 28.3683) -> (-59.9, 25.3683)
  line L114 (-62.4, 23.4) -> (-62.9, 23.9)
  line L115 (-62.4, 21.9) -> (-62.4, 23.4)
  line L116 (-62.9, 21.4) -> (-62.4, 21.9)
  line L117 (-66.9, 21.4) -> (-62.9, 21.4)
  line L118 (-67.4, 21.9) -> (-66.9, 21.4)
  line L119 (-67.4, 23.4) -> (-67.4, 21.9)
  line L120 (-66.9, 23.9) -> (-67.4, 23.4)
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extrude "Extrude2" cut sketch "Sketch2" against normal blind 10
move "Move1"
sketch "Sketch3" plane through (0, 0, -2) normal (0, 0, 1) x axis (-1, 0, 0)
  line L1 (-98.627, 83.52) -> (30, 83.52)
  line L2 (-98.627, -30) -> (-98.627, 83.52)
  line L3 (30, -30) -> (-98.627, -30)
  line L4 (30, 83.52) -> (30, -30)
  circle C1 centre (-66.2, 17.5) radius 1.5
  circle C2 centre (-66.2, 45.5) radius 1.5
  circle C3 centre (-15, 2.5) radius 1.5
  circle C4 centre (-14, 50.8) radius 1.5
  circle C5 centre (-15, 2.5) radius 3
  circle C6 centre (-14, 50.8) radius 3
  circle C7 centre (-66.2, 17.5) radius 3
  circle C8 centre (-66.2, 45.5) radius 3
  concentric C3 C5
  concentric C4 C6
  concentric C1 C7
  concentric C2 C8
  dimension "d9" diameter C5 = 6
  dimension "d10" diameter C6 = 6
  dimension "d11" diameter C7 = 6
  dimension "d12" diameter C8 = 6
extrude "Extrude3" add sketch "Sketch3" profile of C1 C2 C3 C4 C5 C6 C7 C8 along normal blind 2
sketch "Sketch4" plane through (0, 0, -4) normal (0, 0, -1) x axis (1, 0, 0)
  line L1 (-30, 83.52) -> (98.627, 83.52)
  line L2 (-30, -30) -> (-30, 83.52)
  line L3 (98.627, -30) -> (-30, -30)
  line L4 (98.627, 83.52) -> (98.627, -30)
  circle C1 centre (66.2, 17.5) radius 1.5
  circle C2 centre (66.2, 45.5) radius 1.5
  circle C3 centre (15, 2.5) radius 1.5
  circle C4 centre (14, 50.8) radius 1.5
  circle C5 centre (14, 50.8) radius 3
  circle C6 centre (66.2, 45.5) radius 3
  circle C7 centre (15, 2.5) radius 3
  circle C8 centre (66.2, 17.5) radius 3
  concentric C4 C5
  concentric C2 C6
  concentric C3 C7
  concentric C1 C8
  dimension "d15" diameter C5 = 6
  dimension "d16" diameter C6 = 6
  dimension "d17" diameter C7 = 6
  dimension "d18" diameter C8 = 6
offset_faces "OffsetFaces1" distance 2
extrude "Extrude4" cut sketch "Sketch4" profile of C1 C2 C3 C4 C5 C6 C7 C8 against normal blind 2
sketch "Sketch5" plane through (0, 0, -2) normal (0, 0, 1) x axis (-1, 0, 0)
  line L1 (-98.627, 83.52) -> (30, 83.52)
  line L2 (-98.627, -30) -> (-98.627, 83.52)
  line L3 (30, -30) -> (-98.627, -30)
  line L4 (30, 83.52) -> (30, -30)
  line L5 (-98.627, -30) -> (30, -30)
  line L6 (-98.627, -27) -> (-98.627, -30)
  line L7 (30, -27) -> (-98.627, -27)
  line L8 (30, -30) -> (30, -27)
  line L9 (-98.627, 53.2629) -> (0.8042, 53.2629)
  line L10 (-98.627, 63.2629) -> (-98.627, 53.2629)
  line L11 (0.8042, 63.2629) -> (-98.627, 63.2629)
  line L12 (0.8042, 53.2629) -> (0.8042, 63.2629)
  line L13 (30, 83.52) -> (-98.627, 83.52)
  line L14 (30, 63.2629) -> (30, 83.52)
  line L15 (-98.627, 63.2629) -> (30, 63.2629)
  line L16 (-98.627, 83.52) -> (-98.627, 63.2629)
  circle C1 centre (-66.2, 45.5) radius 5
  circle C2 centre (-15, 2.5) radius 5
  circle C3 centre (-66.2, 17.5) radius 5
  circle C4 centre (-14, 50.8) radius 5
  point P9 (30, -30)
  point P10 (30, -30)
  point P20 (30, 63.2629)
  point P7 (-98.627, 83.52)
  point P18 (-98.627, 83.52)
  point P13 (30, -27)
  point P14 (0.8042, 53.2629)
  point P17 (0.8042, 63.2629)
  horizontal L5
  vertical L6
  horizontal L7
  vertical L8
  coincident P9 P10
  horizontal L9
  vertical L10
  horizontal L11
  vertical L12
  horizontal L13
  vertical L14
  horizontal L15
  vertical L16
  coincident L4 P20
  coincident P7 P18
  dimension "d22" distance P10 P13 = 3
  dimension "d23" distance P14 P17 = 10
extrude "Extrude5" cut sketch "Sketch5" profile of L1 L2 L4 L11 L13 L14 L15 L16 against normal blind 10
sketch "Sketch6" plane through (0, 0, -2) normal (0, 0, 1) x axis (-1, 0, 0)
  line L1 (-98.627, 63.2629) -> (30, 63.2629)
  line L2 (-98.627, -30) -> (-98.627, 63.2629)
  line L3 (30, -30) -> (-98.627, -30)
  line L4 (30, 63.2629) -> (30, -30)
  line L5 (27, -30) -> (30, -30)
  line L6 (30, -30) -> (30, -27)
  line L7 (-95.627, 63.2629) -> (-98.627, 63.2629)
  line L8 (-98.627, 63.2629) -> (-98.627, 60.2629)
  line L9 (-95.627, -27) -> (27, -27)
  line L10 (-95.627, 60.2629) -> (-95.627, -27)
  line L11 (27, 60.2629) -> (-95.627, 60.2629)
  line L12 (27, -27) -> (27, 60.2629)
  circle C1 centre (-14, 50.8) radius 5
  circle C2 centre (-66.2, 17.5) radius 5
  circle C3 centre (-15, 2.5) radius 5
  circle C4 centre (-66.2, 45.5) radius 5
  point P5 (30, -30)
  point P10 (30, -30)
  point P3 (-98.627, 63.2629)
  point P14 (-98.627, 63.2629)
  point P11 (27, -30)
  point P13 (30, -27)
  point P15 (-95.627, 63.2629)
  point P17 (-98.627, 60.2629)
  horizontal L5
  vertical L6
  coincident P5 P10
  horizontal L7
  vertical L8
  coincident P3 P14
  horizontal L9
  vertical L10
  horizontal L11
  vertical L12
  dimension "d26" distance P10 P11 = 3
  dimension "d27" distance P10 P13 = 3
  dimension "d28" distance P14 P15 = 3
  dimension "d29" distance P14 P17 = 3
extrude "Extrude6" add sketch "Sketch6" profile of L1 L2 L3 L4 L5 L6 L7 L8 L9 L10 L11 L12 along normal blind 40
sketch "Sketch7" plane through (0, 0, -2) normal (0, 0, 1) x axis (-1, 0, 0)
  line L1 (-95.627, -27) -> (-95.627, 60.2629)
  line L2 (27, -27) -> (-95.627, -27)
  line L3 (27, 60.2629) -> (27, -27)
  line L4 (-95.627, 60.2629) -> (27, 60.2629)
  line L5 (20, -30) -> (30, -30)
  line L6 (20, -20) -> (20, -30)
  line L7 (30, -20) -> (20, -20)
  line L8 (30, -30) -> (30, -20)
  line L9 (-98.627, -27) -> (-95.627, -27)
  line L10 (-98.627, -30) -> (-98.627, -27)
  line L11 (-95.627, -30) -> (-98.627, -30)
  line L12 (-95.627, -27) -> (-95.627, -30)
  line L13 (-88.627, -30) -> (-98.627, -30)
  line L14 (-88.627, -20) -> (-88.627, -30)
  line L15 (-98.627, -20) -> (-88.627, -20)
  line L16 (-98.627, -30) -> (-98.627, -20)
  line L17 (20, -30) -> (30, -20)
  line L18 (-98.627, -20) -> (-88.627, -30)
  circle C1 centre (-14, 50.8) radius 5
  circle C2 centre (-66.2, 17.5) radius 5
  circle C3 centre (-15, 2.5) radius 5
  circle C4 centre (-66.2, 45.5) radius 5
  point P3 (-95.627, -27)
  point P14 (-95.627, -27)
  point P15 (-98.627, -27)
  point P16 (-98.627, -30)
  point P18 (-88.627, -30)
  point P20 (-98.627, -20)
  horizontal L5
  vertical L6
  horizontal L7
  vertical L8
  horizontal L9
  vertical L10
  horizontal L11
  vertical L12
  coincident P3 P14
  horizontal L13
  vertical L14
  horizontal L15
  vertical L16
  perpendicular L17 L18
  dimension "d32" distance P14 P15 = 3
  dimension "d33" distance P16 P18 = 10
  dimension "d34" distance P16 P20 = 10
extrude "Extrude7" add sketch "Sketch7" profile of L1 L2 L3 L17 L18 along normal blind 40
sketch "Sketch8" plane through (0, 30, 0) normal (0, 1, 0) x axis (-1, 0, 0)
  line L1 (-98.627, -4) -> (-98.627, 38)
  line L2 (30, -4) -> (-98.627, -4)
  line L3 (30, 38) -> (30, -4)
  line L4 (-98.627, 38) -> (30, 38)
  line L5 (4, 25.3923) -> (10, 15)
  line L6 (22, 15) -> (10, 15)
  line L7 (-2, 15) -> (4, 25.3923)
  line L8 (16, 25.3923) -> (4, 25.3923)
  line L9 (10, 15) -> (-2, 15)
  line L10 (-8, 25.3923) -> (-2, 15)
  line L11 (10, 15) -> (-2, 15)
  circle C1 centre (10, 15) radius 6
  circle C2 centre (4, 25.3923) radius 3
  circle C3 centre (-2, 15) radius 3
  circle C4 centre (10, 15) radius 3
  circle C5 centre (-8, 25.3923) radius 3
  point P6 (10, 15)
  point P7 (10, 15)
  point P12 (10, 15)
  point P8 (4, 25.3923)
  point P13 (4, 25.3923)
  point P10 (-2, 15)
  point P14 (-2, 15)
  point P16 (-2, 15)
  point P17 (-8, 25.3923)
  point P19 (-8, 25.3923)
  horizontal L6
  coincident P6 P7
  horizontal L8
  coincident P6 P12
  parallel L6 L9
  coincident P8 P13
  coincident P10 P14
  concentric C1 C4
  horizontal L11
  coincident P14 P16
  coincident P17 P19
  dimension "d37" diameter C1 = 12
  dimension "d38" angle L5 L6 = 120
  dimension "d39" distance P7 P8 = 12
  dimension "d40" angle L7 L8 = 120
  dimension "d41" diameter C2 = 6
  dimension "d42" diameter C3 = 6
  dimension "d43" diameter C4 = 6
  dimension "d44" angle L10 L11 = 120
  dimension "d45" distance P16 P17 = 12
  dimension "d46" diameter C5 = 6
extrude "Extrude8" cut sketch "Sketch8" profile of L5 L7 L9 C2 C3 C4 L10 C5 against normal blind 3
sketch "Sketch9" plane through (0, 30, 0) normal (0, 1, 0) x axis (-1, 0, 0)
  line L1 (-98.627, -4) -> (-98.627, 38)
  line L2 (30, -4) -> (-98.627, -4)
  line L3 (30, 38) -> (30, -4)
  line L4 (-98.627, 38) -> (30, 38)
  line L5 (-20, 25.3923) -> (-8, 25.3923)
  line L6 (-29, 25.3923) -> (-20, 25.3923)
  line L7 (-41, 25.3923) -> (-32, 25.3923)
  line L8 (-14, 15) -> (-2, 15)
  line L9 (-26, 15) -> (-14, 15)
  line L10 (-35, 15) -> (-29, 15)
  line L11 (-47, 15) -> (-38, 15)
  line L12 (-53, 25.3923) -> (-44, 25.3923)
  circle C1 centre (4, 25.3923) radius 3
  circle C2 centre (-2, 15) radius 3
  circle C3 centre (-8, 25.3923) radius 3
  circle C4 centre (10, 15) radius 3
  circle C5 centre (-8, 25.3923) radius 3
  circle C6 centre (4, 25.3923) radius 3
  circle C7 centre (-2, 15) radius 3
  circle C8 centre (10, 15) radius 3
  circle C9 centre (-56, 25.3923) radius 3
  circle C10 centre (-44, 25.3923) radius 3
  circle C11 centre (-32, 25.3923) radius 3
  circle C12 centre (-50, 15) radius 3
  circle C13 centre (-38, 15) radius 3
  circle C14 centre (-26, 15) radius 3
  point P10 (-8, 25.3923)
  point P14 (-8, 25.3923)
  point P12 (-2, 15)
  point P18 (-2, 15)
  point P17 (-44, 25.3923)
  point P23 (-44, 25.3923)
  point P16 (-32, 25.3923)
  point P24 (-32, 25.3923)
  point P21 (-38, 15)
  point P26 (-38, 15)
  point P20 (-26, 15)
  point P27 (-26, 15)
  point P28 (-53, 25.3923)
  point P29 (-41, 25.3923)
  point P30 (-29, 25.3923)
  point P31 (-29, 15)
  point P32 (-35, 15)
  point P33 (-47, 15)
  point P15 (-20, 25.3923)
  point P19 (-14, 15)
  point P25 (-50, 15)
  point P22 (-56, 25.3923)
  concentric C3 C5
  concentric C1 C6
  concentric C2 C7
  concentric C4 C8
  coincident P10 P14
  parallel L4 L5
  parallel L5 L6
  parallel L5 L7
  coincident P12 P18
  horizontal L8
  parallel L8 L9
  parallel L9 L10
  parallel L10 L11
  parallel L7 L12
  coincident P17 P23
  coincident P16 P24
  coincident P21 P26
  coincident P20 P27
  coincident C9 P28
  coincident C10 P29
  coincident C11 P30
  coincident C14 P31
  coincident C13 P32
  coincident C12 P33
  dimension "d49" distance P15 P16 = 12
  dimension "d50" distance P16 P17 = 12
  dimension "d51" distance P18 P19 = 12
  dimension "d52" distance P19 P20 = 12
  dimension "d53" distance P20 P21 = 12
  dimension "d54" distance P21 P25 = 12
  dimension "d55" distance P17 P22 = 12
  dimension "d56" diameter C9 = 6
  dimension "d57" diameter C10 = 6
  dimension "d58" diameter C11 = 6
  dimension "d59" diameter C12 = 6
  dimension "d60" diameter C13 = 6
  dimension "d61" diameter C14 = 6
extrude "Extrude9" cut sketch "Sketch9" profile of C9 C10 C11 C12 C13 C14 against normal blind 3
sketch "Sketch10" plane through (0, 30, 0) normal (0, 1, 0) x axis (-1, 0, 0)
  line L1 (-98.627, -4) -> (-98.627, 38)
  line L2 (30, -4) -> (-98.627, -4)
  line L3 (30, 38) -> (30, -4)
  line L4 (-98.627, 38) -> (30, 38)
  line L5 (13, 15) -> (10, 15)
  line L6 (-98.627, 15) -> (-50, 15)
  line L7 (-81.627, 25.3923) -> (-98.627, 25.3923)
  line L8 (-81.627, 15) -> (-98.627, 15)
  line L9 (-78.627, 25.3923) -> (-56, 25.3923)
  line L10 (-98.627, 25.3923) -> (-84.627, 25.3923)
  circle C1 centre (-38, 15) radius 3
  circle C2 centre (-44, 25.3923) radius 3
  circle C3 centre (-50, 15) radius 3
  circle C4 centre (-26, 15) radius 3
  circle C5 centre (-32, 25.3923) radius 3
  circle C6 centre (-56, 25.3923) radius 3
  circle C7 centre (4, 25.3923) radius 3
  circle C8 centre (-2, 15) radius 3
  circle C9 centre (-8, 25.3923) radius 3
  circle C10 centre (10, 15) radius 3
  circle C11 centre (10, 15) radius 3
  circle C12 centre (-81.627, 25.3923) radius 3
  circle C13 centre (-81.627, 15) radius 3
  point P11 (10, 15)
  point P17 (10, 15)
  point P18 (13, 15)
  point P4 (-50, 15)
  point P19 (-50, 15)
  point P20 (-98.627, 15)
  point P7 (-56, 25.3923)
  point P21 (-56, 25.3923)
  point P22 (-98.627, 25.3923)
  point P24 (-81.627, 15)
  point P23 (-81.627, 25.3923)
  point P25 (-81.627, 25.3923)
  point P26 (-78.627, 25.3923)
  point P27 (-84.627, 25.3923)
  point P28 (-81.627, 15)
  concentric C10 C11
  coincident P11 P17
  coincident C10 P18
  horizontal L5
  coincident P4 P19
  coincident L1 P20
  perpendicular L1 L6
  coincident P7 P21
  coincident L1 P22
  perpendicular L1 L9
  perpendicular L1 L7
  coincident L6 P24
  coincident P23 P25
  coincident C12 P26
  coincident C12 P27
  collinear L9 L10
  coincident P24 P28
  dimension "d64" distance P22 P23 = 17
  dimension "d65" distance P20 P24 = 17
  dimension "d66" diameter C12 = 6
  dimension "d67" diameter C13 = 6
extrude "Extrude10" cut sketch "Sketch10" profile of L6 L8 C12 C13 against normal blind 1
sketch "Sketch11" plane through (0, 29, 0) normal (0, 1, 0) x axis (-1, 0, 0)
  circle C1 centre (-81.627, 25.3923) radius 3
  circle C2 centre (-81.627, 25.3923) radius 2
  concentric C1 C2
  dimension "d70" diameter C2 = 4
sketch "Sketch12" plane through (0, 29, 0) normal (0, 1, 0) x axis (-1, 0, 0)
  circle C1 centre (-81.627, 15) radius 3
  circle C2 centre (-81.627, 15) radius 2
  concentric C1 C2
  dimension "d71" diameter C2 = 4
extrude "Extrude11" cut sketch "Sketch11" + "Sketch12" profile of S1:C2 S2:C2 blind -4
chamfer "Chamfer1" distance 5
chamfer "Chamfer2" distance 5
delete_face "DeleteFace1"
delete_face "DeleteFace2"
chamfer "Chamfer3" distance 5
chamfer "Chamfer4" distance 8
delete_face "DeleteFace3"
chamfer "Chamfer5" distance 8
delete_face "DeleteFace4"
delete_face "DeleteFace5"
chamfer "Chamfer6" distance 8
chamfer "Chamfer7" distance 8
delete_face "DeleteFace6"
delete_face "DeleteFace7"
chamfer "Chamfer8" distance 3
chamfer "Chamfer9" distance 3
sketch "Sketch13" plane through (0, 0, 38) normal (0, 0, 1) x axis (-1, 0, 0)
  line L1 (-98.627, 60.2629) -> (-95.627, 63.2629)
  line L2 (-98.627, -27) -> (-98.627, 60.2629)
  line L3 (-95.627, -30) -> (-98.627, -27)
  line L4 (27, -30) -> (-95.627, -30)
  line L5 (30, -27) -> (27, -30)
  line L6 (30, 60.2629) -> (30, -27)
  line L7 (27, 63.2629) -> (30, 60.2629)
  line L8 (-95.627, 63.2629) -> (27, 63.2629)
  line L9 (19, 60.2629) -> (-87.627, 60.2629)
  line L10 (27, 52.2629) -> (19, 60.2629)
  line L11 (27, -19) -> (27, 52.2629)
  line L12 (19, -27) -> (27, -19)
  line L13 (-87.627, -27) -> (19, -27)
  line L14 (-95.627, -19) -> (-87.627, -27)
  line L15 (-95.627, 52.2629) -> (-95.627, -19)
  line L16 (-87.627, 60.2629) -> (-95.627, 52.2629)
  line L17 (23, -23) -> (28.5, -28.5)
  line L18 (-91.627, -23) -> (-97.127, -28.5)
  line L19 (-97.127, 61.7629) -> (-91.627, 56.2629)
  line L20 (23, 56.2629) -> (28.5, 61.7629)
  circle C1 centre (25.75, 59.0129) radius 2
  circle C2 centre (25.75, -25.75) radius 2
  circle C3 centre (-94.377, -25.75) radius 2
  circle C4 centre (-94.377, 59.0129) radius 2
  point P18 (28.5, -28.5)
  point P19 (23, -23)
  point P20 (-97.127, -28.5)
  point P21 (-91.627, -23)
  point P22 (-91.627, 56.2629)
  point P23 (-97.127, 61.7629)
  point P24 (28.5, 61.7629)
  point P25 (23, 56.2629)
  point P26 (25.75, 59.0129)
  point P27 (25.75, -25.75)
  point P28 (-94.377, -25.75)
  point P29 (-94.377, 59.0129)
  midpoint L5 P18
  midpoint L12 P19
  midpoint L3 P20
  midpoint L14 P21
  midpoint L16 P22
  midpoint L1 P23
  midpoint L7 P24
  midpoint L10 P25
  midpoint L20 P26
  midpoint L17 P27
  midpoint L18 P28
  midpoint L19 P29
  dimension "d83" diameter C1 = 4
  dimension "d84" diameter C2 = 4
  dimension "d85" diameter C3 = 4
  dimension "d86" diameter C4 = 4
extrude "Extrude12" cut sketch "Sketch13" profile of L17 L18 L19 L20 C1 C2 C3 C4 against normal blind 3
sketch "Sketch14" plane through (0, 0, 38) normal (0, 0, 1) x axis (-1, 0, 0)
  line L1 (-98.627, 60.2629) -> (-95.627, 63.2629)
  line L2 (-98.627, -27) -> (-98.627, 60.2629)
  line L3 (-95.627, -30) -> (-98.627, -27)
  line L4 (27, -30) -> (-95.627, -30)
  line L5 (30, -27) -> (27, -30)
  line L6 (30, 60.2629) -> (30, -27)
  line L7 (27, 63.2629) -> (30, 60.2629)
  line L8 (-95.627, 63.2629) -> (27, 63.2629)
  line L9 (19, 60.2629) -> (-87.627, 60.2629)
  line L10 (27, 52.2629) -> (19, 60.2629)
  line L11 (27, -19) -> (27, 52.2629)
  line L12 (19, -27) -> (27, -19)
  line L13 (-87.627, -27) -> (19, -27)
  line L14 (-95.627, -19) -> (-87.627, -27)
  line L15 (-95.627, 52.2629) -> (-95.627, -19)
  line L16 (-87.627, 60.2629) -> (-95.627, 52.2629)
  circle C1 centre (-94.377, -25.75) radius 2
  circle C2 centre (-94.377, 59.0129) radius 2
  circle C3 centre (25.75, -25.75) radius 2
  circle C4 centre (25.75, 59.0129) radius 2
extrude "Extrude13" new body sketch "Sketch14" along normal blind 3
move "Move2"
offset_faces "OffsetFaces2" distance 0.05
sketch "Sketch15" plane through (0, 0, 61) normal (0, 0, 1) x axis (-1, 0, 0)
  line L1 (-95.627, 63.2629) -> (27, 63.2629)
  line L2 (-98.627, 60.2629) -> (-95.627, 63.2629)
  line L3 (-98.627, -27) -> (-98.627, 60.2629)
  line L4 (-95.627, -30) -> (-98.627, -27)
  line L5 (27, -30) -> (-95.627, -30)
  line L6 (30, -27) -> (27, -30)
  line L7 (30, 60.2629) -> (30, -27)
  line L8 (27, 63.2629) -> (30, 60.2629)
  circle C1 centre (-94.377, 59.0129) radius 1.95
  circle C2 centre (25.75, 59.0129) radius 1.95
  circle C3 centre (25.75, -25.75) radius 1.95
  circle C4 centre (-94.377, -25.75) radius 1.95
extrude "Extrude14" add sketch "Sketch15" profile of C1 C2 C3 C4 against normal blind 5
move "Move3"
chamfer "Chamfer10" distance 3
